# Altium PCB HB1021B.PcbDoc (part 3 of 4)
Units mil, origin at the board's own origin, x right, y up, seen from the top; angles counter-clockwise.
Board outline 4729.44 x 3075.9 mil, 2 copper layers (Top Layer, Bottom Layer); 113 components, 113 nets, 422 pads, 478 vias.
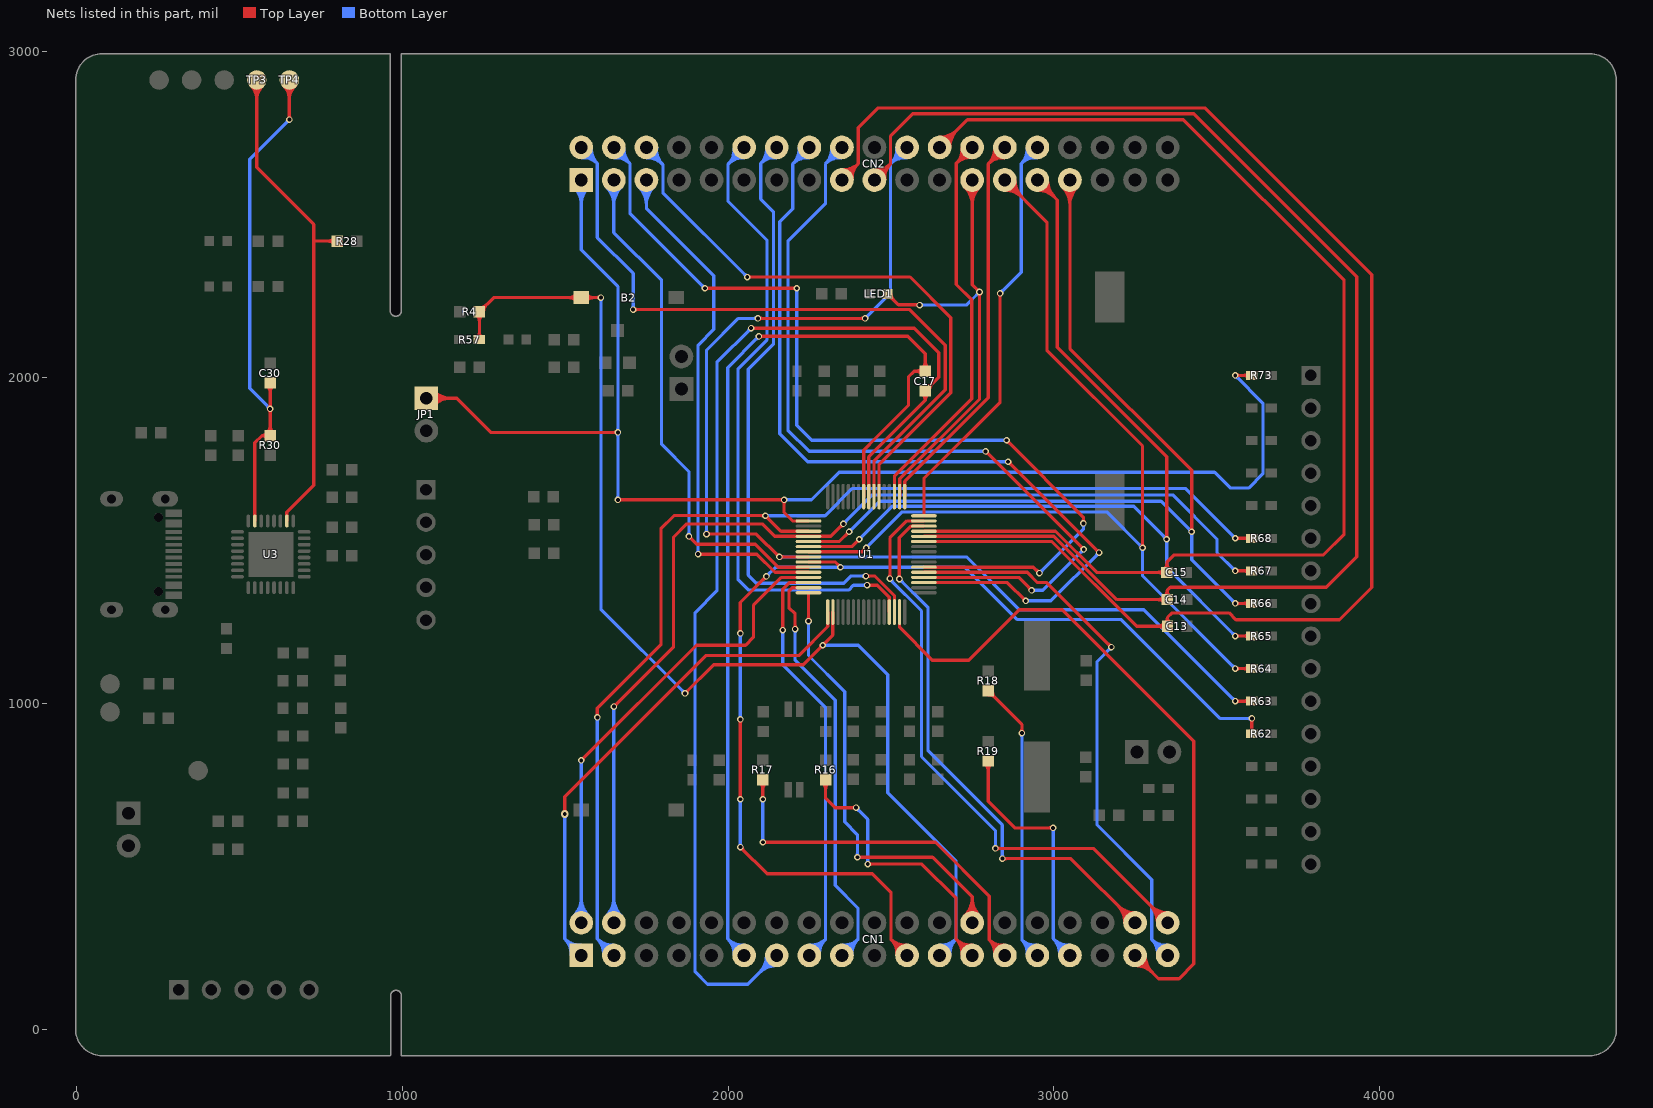
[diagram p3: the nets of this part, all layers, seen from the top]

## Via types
v1: diameter 20, hole 12, Top Layer to Bottom Layer, tented both sides, 451 vias
v2: diameter 23.62, hole 11.81, Top Layer to Bottom Layer, tented both sides, 20 vias
v3: diameter 122.05, hole 122.05, Top Layer to Bottom Layer, tented both sides, 4 vias
v4: diameter 39.37, hole 23.62, Top Layer to Bottom Layer, tented both sides, 2 vias
v5: diameter 30, hole 20, Top Layer to Bottom Layer, tented both sides, 1 vias

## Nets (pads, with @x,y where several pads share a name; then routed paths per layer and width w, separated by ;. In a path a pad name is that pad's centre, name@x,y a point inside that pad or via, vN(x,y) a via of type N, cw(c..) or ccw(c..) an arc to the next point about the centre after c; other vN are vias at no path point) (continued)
PB0: C13.1 CN2.17 U1.27 | length 4788.3
  Top Layer w10: CN2.17@2349.61,2606.79 2400,2657.18 ; CN2.17@2350.57,2628.18 ccw(c2352.57,2672.53) 2383.96,2641.14 ccw(c2415.35,2609.75) CN2.17@2371,2607.75 ; CN2.17@2351.02,2638.17 ccw(c2353.95,2703.22) 2400,2657.18 ; CN2.17@2380.99,2608.2 cw(c2446.04,2611.14) 2400,2657.18 ; U1.27@2601.43,1497.16 2994.42,1497.16 3254.57,1237 C13.1@3349,1237 3349,1264 ; C13.1@3340.16,1228.16 ccw(c3318.82,1206.82) 3318.82,1237 ccw(c3318.82,1267.18) C13.1@3340.16,1245.84 ; C13.1@3340.91,1246.53 ccw(c3326.09,1264) 3349,1264 ; C13.1@3357.09,1246.53 cw(c3371.91,1264) 3349,1264 ; 2400,2657.18 2400,2767 2461,2828 3464.09,2828 3976,2316.09 3976,1356 3877,1257 3559,1257 3538,1278 3363,1278 3349,1264
PB1: C14.1 CN2.19 U1.28 | length 4427.3
  Top Layer w10: CN2.19@2449.61,2606.79 2499.02,2656.2 ; CN2.19@2450.88,2628.17 ccw(c2453.4,2670.37) 2483.29,2640.47 ccw(c2513.18,2610.58) CN2.19@2470.99,2608.06 ; CN2.19@2451.48,2638.15 ccw(c2455.17,2700.05) 2499.02,2656.2 ; CN2.19@2480.97,2608.66 cw(c2542.87,2612.35) 2499.02,2656.2 ; U1.28@2601.43,1512.91 2999.88,1512.91 3193.79,1319 C14.1@3348,1319 3348,1347 ; C14.1@3339.16,1310.16 ccw(c3317.82,1288.82) 3317.82,1319 ccw(c3317.82,1349.18) C14.1@3339.16,1327.84 ; C14.1@3339.66,1328.31 ccw(c3322.89,1347) 3348,1347 ; C14.1@3356.35,1328.31 cw(c3373.11,1347) 3348,1347 ; 2499.02,2656.2 2499.02,2742.02 2567,2810 3430,2810 3930,2310 3930,1450 3837,1357 3358,1357 3348,1347
PB2: C15.1 CN2.24 U1.29 | length 3964.7
  Top Layer w10: U1.29@2601.43,1528.65 3005.35,1528.65 3131.89,1402.11 C15.1@3347.29,1402.11 3347.29,1433.29 3370,1456 3828,1456 3891,1519 3891,2299 3398,2792 2734.82,2792 CN2.24@2649.61,2706.79 ; CN2.24@2649.61,2728.21 ccw(c2649.61,2779.91) 2686.17,2743.35 ccw(c2722.73,2706.79) CN2.24@2671.02,2706.79 ; CN2.24@2649.61,2738.21 ccw(c2649.61,2814.05) 2703.24,2760.42 ccw(c2756.87,2706.79) CN2.24@2681.02,2706.79 ; C15.1@3338.45,1393.27 ccw(c3317.11,1371.93) 3317.11,1402.11 ccw(c3317.11,1432.28) 3338.45,1410.94 ccw(c3317.11,1432.28) 3347.29,1432.28 ccw(c3377.46,1432.28) C15.1@3356.13,1410.94
PB3: CN2.31 R66.1 U1.54 | length 3193.8
  Top Layer w10: U1.54@2247.1,1497.16 2342.1,1497.16 v1(2372,1527.06) ; v1@2367,1527.06 cw(c2354.93,1527.06) 2363.46,1518.52 cw(c2372,1509.98) v1@2372,1522.06 ; CN2.31@3027.39,2584.57 cw(c2973.76,2530.94) 3049.61,2530.94 cw(c3125.45,2530.94) CN2.31@3071.82,2584.57 ; CN2.31@3034.46,2591.64 cw(c2997.9,2555.08) 3049.61,2555.08 cw(c3101.31,2555.08) CN2.31@3064.75,2591.64 ; CN2.31@3049.61,2606.79 3049.61,2089.39 3423.34,1715.66 v1(3423.34,1527.06) ; v1@3419.8,1530.59 ccw(c3411.27,1539.13) 3423.34,1539.13 ccw(c3435.41,1539.13) v1@3426.87,1530.59 ; v1(3557,1307) R66.1@3608,1307 ; v1@3560.54,1303.46 cw(c3569.07,1294.93) 3569.07,1307 cw(c3569.07,1319.07) v1@3560.54,1310.54 ; R66.1@3598.07,1300.79 ccw(c3583.08,1285.8) 3583.08,1307 ccw(c3583.08,1328.2) R66.1@3598.07,1313.21
  Bottom Layer w10: v1(2372,1527.06) 2465.94,1621 3329.39,1621 v1(3423.34,1527.06) 3423.34,1440.66 v1(3557,1307) ; v1@2372,1532.06 ccw(c2372,1544.13) 2380.54,1535.59 ccw(c2389.07,1527.06) v1@2377,1527.06 ; v1@3418.34,1527.06 ccw(c3406.27,1527.06) 3414.8,1535.59 ccw(c3423.34,1544.13) v1@3423.34,1532.06 ; v1@3419.8,1523.52 cw(c3411.27,1514.98) 3423.34,1514.98 cw(c3435.41,1514.98) v1@3426.87,1523.52 ; v1@3552,1307 ccw(c3539.93,1307) 3548.46,1315.54 ccw(c3557,1324.07) v1@3557,1312
PB4: CN2.29 R65.1 U1.55 | length 3262.7
  Top Layer w10: U1.55@2247.1,1481.41 2380.41,1481.41 v1(2403,1504) ; v1@2398,1504 cw(c2385.93,1504) 2394.46,1495.46 cw(c2403,1486.93) v1@2403,1499 ; CN2.29@2949.61,2575.37 cw(c2949.61,2499.52) 3003.24,2553.16 cw(c3056.87,2606.79) CN2.29@2981.02,2606.79 ; CN2.29@2949.61,2585.37 cw(c2949.61,2533.67) 2986.17,2570.23 cw(c3022.73,2606.79) CN2.29@2971.02,2606.79 ; CN2.29@2949.61,2606.79 3011,2545.39 3011,2093 3346.39,1757.61 v1(3346.39,1504) ; v1@3342.86,1507.54 ccw(c3334.32,1516.07) 3346.39,1516.07 ccw(c3358.47,1516.07) v1@3349.93,1507.54 ; v1@3556,1207 v1(3557,1207) R65.1@3608,1207 ; v1@3560.54,1203.46 cw(c3569.07,1194.93) 3569.07,1207 cw(c3569.07,1219.07) v1@3560.54,1210.54 ; R65.1@3598.07,1200.79 ccw(c3583.08,1185.8) 3583.08,1207 ccw(c3583.08,1228.2) R65.1@3598.07,1213.21
  Bottom Layer w10: v1(2403,1504) 2504,1605 3245.39,1605 v1(3346.39,1504) ; v1@2403,1509 ccw(c2403,1521.07) 2411.54,1512.54 ccw(c2420.07,1504) v1@2408,1504 ; v1@3341.39,1504 ccw(c3329.32,1504) 3337.86,1512.54 ccw(c3346.39,1521.07) v1@3346.39,1509 ; v1@3342.86,1500.46 cw(c3334.32,1491.93) 3346.39,1491.93 cw(c3358.47,1491.93) v1@3349.93,1500.46 ; v1@3346.39,1504.61 v1(3346.39,1504) ; v1@3552,1207 ccw(c3539.93,1207) 3548.46,1215.54 ccw(c3557,1224.07) v1@3557,1212 ; v1(3557,1207) 3346.39,1417.61 v1(3346.39,1504)
PB5: CN2.27 R64.1 U1.56 | length 3331.4
  Top Layer w10: U1.56@2247.1,1465.66 2412.46,1465.66 v1(2424.27,1477.47) ; v1@2419.27,1477.47 cw(c2407.2,1477.47) 2415.73,1468.94 cw(c2424.27,1460.4) v1@2424.27,1472.47 ; CN2.27@2849.61,2575.37 cw(c2849.61,2499.52) 2903.24,2553.16 cw(c2956.87,2606.79) CN2.27@2881.02,2606.79 ; CN2.27@2849.61,2585.37 cw(c2849.61,2533.67) 2886.17,2570.23 cw(c2922.73,2606.79) CN2.27@2871.02,2606.79 ; CN2.27@2849.61,2606.79 2979,2477.39 2979,2084 3272.37,1790.63 v1(3272.37,1478.03) ; v1@3268.83,1481.56 ccw(c3260.3,1490.1) 3272.37,1490.1 ccw(c3284.44,1490.1) v1@3275.9,1481.56 ; v1(3557,1107) R64.1@3608,1107 ; v1@3560.54,1103.46 cw(c3569.07,1094.93) 3569.07,1107 cw(c3569.07,1119.07) v1@3560.54,1110.54 ; R64.1@3598.07,1100.79 ccw(c3583.08,1085.8) 3583.08,1107 ccw(c3583.08,1128.2) R64.1@3598.07,1113.21
  Bottom Layer w10: v1@2424.27,1478.03 2534.24,1588 3162.39,1588 v1(3272.37,1478.03) 3272.37,1391.63 v1(3557,1107) ; v1@2424.27,1482.47 ccw(c2424.27,1493.2) 2431.85,1485.62 ; v1@2429.27,1477.47 cw(c2442.68,1477.47) 2433.2,1486.96 ; v1@3267.37,1478.03 ccw(c3255.3,1478.03) 3263.83,1486.56 ccw(c3272.37,1495.1) v1@3272.37,1483.03 ; v1@3268.83,1474.49 cw(c3260.3,1465.96) 3272.37,1465.96 cw(c3284.44,1465.96) v1@3275.9,1474.49 ; v1@3552,1107 ccw(c3539.93,1107) 3548.46,1115.54 ccw(c3557,1124.07) v1@3557,1112
PB6: CN2.22 R63.1 U1.57 | length 4070.1
  Top Layer w10: v1(1934,1520) 2087,1520 2157.09,1449.91 U1.57@2247.1,1449.91 ; v1@1937.54,1516.46 cw(c1946.07,1507.93) 1946.07,1520 cw(c1946.07,1532.07) v1@1937.54,1523.54 ; v1(2092,2182) v1(2421,2182) ; v1@2095.54,2178.46 cw(c2104.07,2169.93) 2104.07,2182 cw(c2104.07,2194.07) v1@2095.54,2185.54 ; 2147.91,1459.09 ccw(c2158,1469.19) v1@2158,1454.91 ; 2150.11,1456.89 cw(c2143.13,1449.91) v1@2153,1449.91 ; v1@2161.54,1446.38 cw(c2170.07,1437.84) 2170.07,1449.91 cw(c2170.07,1461.98) v1@2161.54,1453.45 ; v1@2417.46,2178.46 ccw(c2408.93,2169.93) 2408.93,2182 ccw(c2408.93,2194.07) v1@2417.46,2185.54 ; v1(3557,1007) R63.1@3608,1007 ; v1@3560.54,1003.46 cw(c3569.07,994.93) 3569.07,1007 cw(c3569.07,1019.07) v1@3560.54,1010.54 ; R63.1@3598.07,1000.79 ccw(c3583.08,985.8) 3583.08,1007 ccw(c3583.08,1028.2) R63.1@3598.07,1013.21
  Bottom Layer w10: v1@1930.46,1523.54 ccw(c1921.93,1532.07) 1934,1532.07 ccw(c1946.07,1532.07) v1@1937.54,1523.54 ; v1(1934,1520) 1934,2084 2032,2182 v1(2092,2182) ; v1@2088.46,2178.46 ccw(c2079.93,2169.93) 2079.93,2182 ccw(c2079.93,2194.07) v1@2088.46,2185.54 ; v1(2158,1449.91) 2732.09,1449.91 2894,1288 3276,1288 v1(3557,1007) ; v1@2161.54,1446.38 cw(c2170.07,1437.84) 2170.07,1449.91 cw(c2170.07,1461.98) v1@2161.54,1453.45 ; v1(2421,2182) 2499.02,2260.02 2499.02,2656.2 ; v1@2421,2187 ccw(c2421,2199.07) 2429.54,2190.54 ccw(c2438.07,2182) v1@2426,2182 ; CN2.22@2518.22,2705.46 cw(c2452.55,2702.68) 2499.03,2656.21 ; CN2.22@2528.21,2705.88 cw(c2483.44,2703.99) 2515.13,2672.31 cw(c2546.81,2640.63) CN2.22@2548.7,2685.39 ; CN2.22@2548.28,2675.4 ccw(c2545.5,2609.73) 2499.03,2656.21 ; CN2.22@2549.61,2706.79 2499.02,2656.2 ; v1@3552,1007 ccw(c3539.93,1007) 3548.46,1015.54 ccw(c3557,1024.07) v1@3557,1012
PB7: CN1.21 R62.1 U1.58 | length 3938.2
  Top Layer w10: v1@2034.37,709.54 ccw(c2025.84,718.07) 2037.91,718.07 ccw(c2049.98,718.07) v1@2041.45,709.54 ; v1@2034.37,947.46 cw(c2025.84,938.93) 2037.91,938.93 cw(c2049.98,938.93) v1@2041.45,947.46 ; v1@2034.37,1218.54 ccw(c2025.84,1227.07) 2037.91,1227.07 ccw(c2049.98,1227.07) v1@2041.45,1218.54 ; v1@2037.91,553.91 cw(c2037.91,541.84) 2046.45,550.37 cw(c2054.98,558.91) v1@2042.91,558.91 ; v1(2037.91,558.91) 2119.82,477 2443.17,477 2500,420.17 2500,276.39 ; v1(2037.91,706) v1(2037.91,951) ; v1(2037.91,1215) 2037.91,1309.91 v1(2118,1390) ; v1@2113,1390 cw(c2100.93,1390) 2109.46,1381.46 cw(c2118,1372.93) v1@2118,1385 ; U1.58@2247.1,1434.17 2328.83,1434.17 v1(2345,1418) ; v1@2340,1418 ccw(c2327.93,1418) 2336.46,1426.54 ccw(c2345,1435.07) v1@2345,1423 ; CN1.21@2518.24,228.57 ccw(c2455.73,232.12) 2500,276.39 ; CN1.21@2528.22,228 ccw(c2485.61,230.42) 2515.79,260.6 ccw(c2545.97,290.78) CN1.21@2548.39,248.17 ; CN1.21@2547.82,258.15 cw(c2544.27,320.66) 2500,276.39 ; CN1.21@2549.61,226.79 2500,276.39 ; R62.1@3601.79,913.21 ccw(c3586.8,928.2) 3608,928.2 ccw(c3629.2,928.2) R62.1@3614.21,913.21 ; v1@3604.46,950.46 cw(c3595.93,941.93) 3608,941.93 cw(c3620.07,941.93) v1@3611.54,950.46 ; R62.1@3608,907 v1(3608,954)
  Bottom Layer w10: v1@2034.37,562.45 ccw(c2025.84,570.98) 2037.91,570.98 ccw(c2049.98,570.98) v1@2041.45,562.45 ; v1@2034.37,702.46 cw(c2025.84,693.93) 2037.91,693.93 cw(c2049.98,693.93) v1@2041.45,702.46 ; v1@2034.37,954.54 ccw(c2025.84,963.07) 2037.91,963.07 ccw(c2049.98,963.07) v1@2041.45,954.54 ; v1@2034.37,1211.46 cw(c2025.84,1202.93) 2037.91,1202.93 cw(c2049.98,1202.93) v1@2041.45,1211.46 ; v1(2037.91,558.91) v1(2037.91,706) ; v1(2037.91,951) v1(2037.91,1215) ; v1(2118,1390) 2146,1418 v1(2345,1418) 2727,1418 2887,1258 3206,1258 3510,954 v1(3608,954) ; v1@2118,1395 ccw(c2118,1407.07) 2126.54,1398.54 ccw(c2135.07,1390) v1@2123,1390 ; v1@2341.46,1414.46 ccw(c2332.93,1405.93) 2332.93,1418 ccw(c2332.93,1430.07) v1@2341.46,1421.54 ; v1@2348.54,1414.46 cw(c2357.07,1405.93) 2357.07,1418 cw(c2357.07,1430.07) v1@2348.54,1421.54 ; v1@3604.46,950.46 ccw(c3595.93,941.93) 3595.93,954 ccw(c3595.93,966.07) v1@3604.46,957.54
PB8: CN2.3 U1.59 | length 1833.8
  Top Layer w10: v1@1880,1508 cw(c1880,1495.93) 1888.54,1504.46 cw(c1897.07,1513) v1@1885,1513 ; v1(1880,1513) 1904,1489 2084,1489 2154.58,1418.42 U1.59@2247.1,1418.42
  Bottom Layer w10: CN2.3@1627.39,2584.57 cw(c1573.76,2530.94) 1649.61,2530.94 cw(c1725.45,2530.94) CN2.3@1671.82,2584.57 ; CN2.3@1634.46,2591.64 cw(c1597.9,2555.08) 1649.61,2555.08 cw(c1701.31,2555.08) CN2.3@1664.75,2591.64 ; CN2.3@1649.61,2606.79 1649.61,2445.39 1796,2299 1796,1796 1880,1712 v1(1880,1513) ; v1@1876.46,1516.54 ccw(c1867.93,1525.07) 1880,1525.07 ccw(c1892.07,1525.07) v1@1883.54,1516.54
PB9: CN2.5 U1.60 | length 1854.3
  Top Layer w10: v1(1908,1458.27) 2088.73,1458.27 2144.33,1402.67 U1.60@2247.1,1402.67 ; v1@1911.54,1454.73 cw(c1920.07,1446.2) 1920.07,1458.27 cw(c1920.07,1470.34) v1@1911.54,1461.8
  Bottom Layer w10: CN2.5@1727.39,2584.57 cw(c1673.76,2530.94) 1749.61,2530.94 cw(c1825.45,2530.94) CN2.5@1771.82,2584.57 ; CN2.5@1734.46,2591.64 cw(c1697.9,2555.08) 1749.61,2555.08 cw(c1801.31,2555.08) CN2.5@1764.75,2591.64 ; CN2.5@1749.61,2606.79 1749.61,2519.39 1956,2313 1956,2148 1908,2100 v1(1908,1458.27) ; v1@1904.46,1461.8 ccw(c1895.93,1470.34) 1908,1470.34 ccw(c1920.07,1470.34) v1@1911.54,1461.8
PB10: CN1.36 U1.30 | length 1990.3
  Top Layer w10: v1@2522.46,1385.54 ccw(c2513.93,1394.07) 2526,1394.07 ccw(c2538.07,1394.07) v1@2529.54,1385.54 ; v1(2526,1382) 2526,1508.77 2561.63,1544.4 U1.30@2601.43,1544.4 ; 2557.98,1540.75 cw(c2566.98,1531.75) 2566.98,1544.48 ccw(c2565.79,1534.89) 2558.95,1541.73 ; v1(2842,523.73) 3052.66,523.73 CN1.36@3249.61,326.79 ; v1@2845.54,520.2 cw(c2854.07,511.66) 2854.07,523.73 cw(c2854.07,535.8) v1@2845.54,527.27 ; CN1.36@3218.19,326.79 ccw(c3142.34,326.79) 3195.97,380.42 ccw(c3249.61,434.05) CN1.36@3249.61,358.21 ; CN1.36@3228.19,326.79 ccw(c3176.48,326.79) 3213.04,363.35 ccw(c3249.61,399.91) CN1.36@3249.61,348.21
  Bottom Layer w10: v1@2526,1377 cw(c2526,1364.93) 2534.54,1373.46 cw(c2543.07,1382) v1@2531,1382 ; v1(2526,1382) 2614,1294 2614,855 2842,627 v1(2842,523.73) ; v1@2838.46,527.27 ccw(c2829.93,535.8) 2842,535.8 ccw(c2854.07,535.8) v1@2845.54,527.27
PB11: CN1.38 U1.31 | length 2106.9
  Top Layer w10: v1@2493.46,1386.54 ccw(c2484.93,1395.07) 2497,1395.07 ccw(c2509.07,1395.07) v1@2500.54,1386.54 ; v1(2497,1383) 2497,1508 2549.15,1560.15 U1.31@2601.43,1560.15 ; v1(2821,555) 3121.39,555 CN1.38@3349.61,326.79 ; v1@2824.54,551.46 cw(c2833.07,542.93) 2833.07,555 cw(c2833.07,567.07) v1@2824.54,558.54 ; CN1.38@3318.19,326.79 ccw(c3242.34,326.79) 3295.97,380.42 ccw(c3349.61,434.05) CN1.38@3349.61,358.21 ; CN1.38@3328.19,326.79 ccw(c3276.48,326.79) 3313.04,363.35 ccw(c3349.61,399.91) CN1.38@3349.61,348.21
  Bottom Layer w10: v1(2497,1383) 2497,1381 2594,1284 2594,837 2821,610 v1(2821,555) ; v1@2502,1383 ccw(c2518.9,1383) 2506.95,1371.05 ; v1@2817.46,558.54 ccw(c2808.93,567.07) 2821,567.07 ccw(c2833.07,567.07) v1@2824.54,558.54
PB12: CN2.30 U1.32 | length 1490.4
  Top Layer w10: U1.32@2601.43,1575.9 2601.43,1690.43 2835,1924 v1(2835,2259) ; v1@2831.46,2255.46 cw(c2822.93,2246.93) 2835,2246.93 cw(c2847.07,2246.93) v1@2838.54,2255.46
  Bottom Layer w10: v1(2835,2259) 2900,2324 2900,2657.18 ; v1@2835,2264 ccw(c2835,2276.07) 2843.54,2267.54 ccw(c2852.07,2259) v1@2840,2259 ; CN2.30@2918.24,2705.01 cw(c2855.73,2701.46) 2900,2657.18 ; CN2.30@2928.22,2705.57 cw(c2885.61,2703.15) 2915.79,2672.97 cw(c2945.97,2642.79) CN2.30@2948.39,2685.41 ; CN2.30@2947.82,2675.42 ccw(c2944.27,2612.91) 2900,2657.18 ; CN2.30@2949.61,2706.79 2900,2657.18
PB13: CN2.28 U1.33 | length 1389.4
  Top Layer w10: U1.33@2542.38,1634.95 2542.38,1681.38 2799,1938 2799,2656.18 ; CN2.28@2818.22,2705.47 cw(c2752.48,2702.71) 2799,2656.18 ; CN2.28@2828.21,2705.89 cw(c2783.39,2704.01) 2815.11,2672.29 cw(c2846.83,2640.57) CN2.28@2848.71,2685.39 ; CN2.28@2848.29,2675.4 ccw(c2845.53,2609.66) 2799,2656.18 ; CN2.28@2849.61,2706.79 2799,2656.18
  Bottom Layer w10: CN2.28@2849.61,2699.62 CN2.28@2849.61,2706.79
PB14: CN2.25 LED1.2 U1.34 | length 1721.7
  Top Layer w10: LED1.2@2490,2247 cw(c2490,2222.86) 2507.07,2239.93 cw(c2524.14,2257) LED1.2@2500,2257 ; LED1.2@2490,2257 2523,2224 2587,2224 v1(2588,2223) ; U1.34@2526.63,1634.95 2527.38,1635.7 2527.38,1689.38 2772,1934 v1(2772,2263) 2749.61,2285.39 CN2.25@2749.61,2606.79 ; 2573.51,2224 cw(c2573.51,2208.51) v1@2584.46,2219.46 ; CN2.25@2727.39,2584.57 cw(c2673.76,2530.94) 2749.61,2530.94 cw(c2825.45,2530.94) CN2.25@2771.82,2584.57 ; CN2.25@2734.46,2591.64 cw(c2697.9,2555.08) 2749.61,2555.08 cw(c2801.31,2555.08) CN2.25@2764.75,2591.64 ; v1@2767,2263 ccw(c2754.93,2263) 2763.46,2271.54 ccw(c2772,2280.07) v1@2772,2268 ; v1@2768.46,2259.46 cw(c2759.93,2250.93) 2772,2250.93 cw(c2784.07,2250.93) v1@2775.54,2259.46
  Bottom Layer w10: v1(2588,2223) 2732,2223 v1(2772,2263) ; v1@2591.54,2219.46 cw(c2600.07,2210.93) 2600.07,2223 cw(c2600.07,2235.07) v1@2591.54,2226.54 ; v1@2767,2263 cw(c2754.93,2263) 2763.46,2254.46 cw(c2772,2245.93) v1@2772,2258
PB15: CN2.26 U1.35 | length 1381.2
  Top Layer w10: U1.35@2510.88,1634.95 2510.88,1697.88 2748,1935 2748,2239 2701,2286 2701,2658.18 ; CN2.26@2718.27,2704.53 cw(c2658.94,2700.25) 2701,2658.18 ; CN2.26@2728.24,2705.25 cw(c2687.8,2702.33) 2716.47,2673.65 cw(c2745.15,2644.98) CN2.26@2748.06,2685.43 ; CN2.26@2747.35,2675.45 ccw(c2743.06,2616.12) 2701,2658.18 ; CN2.26@2749.61,2706.79 2701,2658.18
PC0: CN2.12 U1.13 | length 2192.1
  Top Layer w10: v1(2427,1363) 2458,1363 2495.13,1325.87 U1.13@2495.13,1280.62 ; v1@2430.54,1359.46 cw(c2439.07,1350.93) 2439.07,1363 cw(c2439.07,1375.07) v1@2430.54,1366.54
  Bottom Layer w10: 2016.27,2671.27 ccw(c1986.81,2700.74) CN2.12@2028.29,2704.73 ; 2017.82,2672.82 cw(c2048.16,2642.49) CN2.12@2049.12,2685.38 ; CN2.12@2018.33,2703.78 cw(c1959.46,2698.11) 2001.28,2656.28 cw(c2047.43,2610.14) CN2.12@2048.9,2675.38 ; CN2.12@2049.61,2706.79 2049.61,2704.61 2000.19,2655.19 2000.19,2540.81 2120,2421 2120,2117 2031,2028 2031,1380 2063,1348 2370,1348 2385,1363 v1(2427,1363) ; v1@2423.46,1359.46 ccw(c2414.93,1350.93) 2414.93,1363 ccw(c2414.93,1375.07) v1@2423.46,1366.54
PC1: CN2.14 U1.14 | length 2140
  Top Layer w10: v1(2423,1391) 2451.21,1391 2510.88,1331.33 U1.14@2510.88,1280.62 ; v1@2426.54,1387.46 cw(c2435.07,1378.93) 2435.07,1391 cw(c2435.07,1403.07) v1@2426.54,1394.54
  Bottom Layer w10: CN2.14@2118.24,2704.92 cw(c2056.34,2701.22) 2100.19,2657.37 ; CN2.14@2128.23,2705.51 cw(c2086.03,2703) 2115.92,2673.1 cw(c2145.81,2643.21) CN2.14@2148.33,2685.41 ; CN2.14@2147.74,2675.43 ccw(c2144.04,2613.52) 2100.19,2657.37 ; CN2.14@2149.61,2706.79 2100.19,2657.37 ; v1@2419.46,1387.46 ccw(c2410.93,1378.93) 2410.93,1391 ccw(c2410.93,1403.07) v1@2419.46,1394.54 ; v1(2423,1391) 2377.17,1391 2355.17,1369 2087,1369 2062,1394 2062,2026 2140,2104 2140,2508.44 2100.19,2548.25 2100.19,2657.37
PC2: CN1.35 U1.15 | length 2336.9
  Top Layer w10: U1.15@2526.63,1280.62 2526.63,1233.37 2627,1133 2739,1133 2894,1288 3026.57,1288 3430,884.57 3430,200.52 3384.48,155 3321.39,155 CN1.35@3249.61,226.79 ; CN1.35@3249.61,195.37 cw(c3249.61,119.52) 3303.24,173.16 cw(c3356.87,226.79) CN1.35@3281.02,226.79 ; CN1.35@3249.61,205.37 cw(c3249.61,153.66) 3286.17,190.23 cw(c3322.73,226.79) CN1.35@3271.02,226.79
PC3: CN2.16 U1.19 | length 2966.4
  Top Layer w10: U1.19@2601.43,1371.17 2857.83,1371.17 v1(2914,1315) ; v1@2860,1737 cw(c2860,1724.93) 2868.54,1733.46 cw(c2877.07,1742) v1@2865,1742 ; v1(2860,1742) v1(3139,1463) ; v1@2909,1315 ccw(c2896.93,1315) 2905.46,1323.54 ccw(c2914,1332.07) v1@2914,1320 ; v1@3134,1463 ccw(c3121.93,1463) 3130.46,1471.54 ccw(c3139,1480.07) v1@3139,1468
  Bottom Layer w10: CN2.16@2218.22,2705.46 cw(c2152.55,2702.68) 2199.03,2656.21 ; CN2.16@2228.21,2705.88 cw(c2183.44,2703.99) 2215.13,2672.31 cw(c2246.81,2640.63) CN2.16@2248.7,2685.39 ; CN2.16@2248.28,2675.4 ccw(c2245.5,2609.73) 2199.03,2656.21 ; CN2.16@2249.61,2706.79 2199.02,2656.2 ; v1@2856.46,1738.46 ccw(c2847.93,1729.93) 2847.93,1742 ccw(c2847.93,1754.07) v1@2856.46,1745.54 ; v1(2860,1742) 2245,1742 2159,1828 2159,2478.31 2199.02,2518.33 2199.02,2656.2 ; v1(2914,1315) 2991,1315 v1(3139,1463) ; v1@2917.54,1311.46 cw(c2926.07,1302.93) 2926.07,1315 cw(c2926.07,1327.07) v1@2917.54,1318.54 ; v1@3134,1463 cw(c3121.93,1463) 3130.46,1454.46 cw(c3139,1445.93) v1@3139,1458
PC4: CN2.18 U1.20 | length 2852
  Top Layer w10: U1.20@2601.43,1386.92 2892.08,1386.92 v1(2931.76,1347.24) ; v1@2791,1769 cw(c2791,1756.93) 2799.54,1765.46 cw(c2808.07,1774) v1@2796,1774 ; v1(2791,1774) v1(3092,1473) ; v1@2926.76,1347.24 ccw(c2914.69,1347.24) 2923.23,1355.77 ccw(c2931.76,1364.31) v1@2931.76,1352.24 ; v1@3087,1473 ccw(c3074.93,1473) 3083.46,1481.54 ccw(c3092,1490.07) v1@3092,1478
  Bottom Layer w10: 2299,2627.28 2299,2656.18 ; 2299.02,2627.26 2299.02,2533.51 2184,2418.48 2184,1839 2249,1774 v1(2791,1774) ; CN2.18@2318.22,2705.47 cw(c2252.48,2702.71) 2299,2656.18 ; CN2.18@2328.21,2705.89 cw(c2283.39,2704.01) 2315.11,2672.29 cw(c2346.83,2640.58) CN2.18@2348.71,2685.39 ; CN2.18@2348.29,2675.4 ccw(c2345.53,2609.66) 2299,2656.18 ; CN2.18@2349.61,2706.79 2299,2656.18 ; v1@2787.46,1770.46 ccw(c2778.93,1761.93) 2778.93,1774 ccw(c2778.93,1786.07) v1@2787.46,1777.54 ; v1(2931.76,1347.24) 2966.24,1347.24 v1(3092,1473) ; v1@2935.3,1343.7 cw(c2943.83,1335.17) 2943.83,1347.24 cw(c2943.83,1359.31) v1@2935.3,1350.77 ; v1@3087,1473 cw(c3074.93,1473) 3083.46,1464.46 cw(c3092,1455.93) v1@3092,1468
PC5: CN1.37 U1.21 | length 1934.7
  Top Layer w10: U1.21@2601.43,1402.67 2918.33,1402.67 2950,1371 2979,1371 v1(3177,1173) ; v1@3172,1173 ccw(c3159.93,1173) 3168.46,1181.54 ccw(c3177,1190.07) v1@3177,1178
  Bottom Layer w10: v1@3172,1173 cw(c3159.93,1173) 3168.46,1164.46 cw(c3177,1155.93) v1@3177,1168 ; v1(3177,1173) 3132.61,1128.61 3132.61,627.35 3301,458.95 3301,275.39 ; CN1.37@3318.27,229.05 ccw(c3258.94,233.33) 3301,275.39 ; CN1.37@3328.24,228.33 ccw(c3287.8,231.25) 3316.47,259.92 ccw(c3345.15,288.6) CN1.37@3348.06,248.15 ; CN1.37@3347.35,258.12 cw(c3343.06,317.45) 3301,275.39 ; CN1.37@3349.61,226.79 3301,275.39
PC6: CN2.4 U1.22 | length 3203.3
  Top Layer w10: v1(1929,2274.5) v1(2211,2274.5) ; v1@1932.54,2270.96 cw(c1941.07,2262.43) 1941.07,2274.5 cw(c1941.07,2286.57) v1@1932.54,2278.04 ; v1@2207.46,2270.96 ccw(c2198.93,2262.43) 2198.93,2274.5 ccw(c2198.93,2286.57) v1@2207.46,2278.04 ; U1.22@2601.43,1418.42 2937.58,1418.42 v1(2956,1400) ; v1@2855,1803 cw(c2855,1790.93) 2863.54,1799.46 cw(c2872.07,1808) v1@2860,1808 ; v1(2855,1808) 3091,1572 v1(3091,1553) ; v1@2951,1400 ccw(c2938.93,1400) 2947.46,1408.54 ccw(c2956,1417.07) v1@2956,1405 ; v1@3087.46,1556.54 ccw(c3078.93,1565.07) 3091,1565.07 ccw(c3103.07,1565.07) v1@3094.54,1556.54
  Bottom Layer w10: CN2.4@1649.61,2706.79 1699.02,2657.37 ; CN2.4@1650.88,2685.41 cw(c1653.4,2643.21) 1683.29,2673.1 cw(c1713.19,2703) CN2.4@1670.99,2705.51 ; CN2.4@1651.48,2675.43 cw(c1655.17,2613.52) 1699.02,2657.37 ; CN2.4@1680.97,2704.92 ccw(c1742.87,2701.22) 1699.02,2657.37 ; v1@1924,2274.5 ccw(c1911.93,2274.5) 1920.46,2283.04 ccw(c1929,2291.57) v1@1929,2279.5 ; v1(1929,2274.5) 1699.02,2504.48 1699.02,2657.37 ; v1@2207.46,2270.96 cw(c2198.93,2262.43) 2211,2262.43 cw(c2223.07,2262.43) v1@2214.54,2270.96 ; v1(2211,2274.5) 2211,1854 2257,1808 v1(2855,1808) ; v1@2851.46,1804.46 ccw(c2842.93,1795.93) 2842.93,1808 ccw(c2842.93,1820.07) v1@2851.46,1811.54 ; v1(2956,1400) 3091,1535 v1(3091,1553) ; v1@2956,1405 ccw(c2956,1417.07) 2964.54,1408.54 ccw(c2973.07,1400) v1@2961,1400 ; v1@3087.46,1549.46 cw(c3078.93,1540.93) 3091,1540.93 cw(c3103.07,1540.93) v1@3094.54,1549.46
PC7: CN2.6 U1.38 | length 2063.9
  Top Layer w10: v1(2059,2309) 2559,2309 2684,2184 2684,1954 2463.64,1733.64 U1.38@2463.64,1634.95 ; v1@2062.54,2305.46 cw(c2071.07,2296.93) 2071.07,2309 cw(c2071.07,2321.07) v1@2062.54,2312.54
  Bottom Layer w10: CN2.6@1749.66,2685.37 cw(c1749.76,2639.82) 1781.97,2672.03 ; CN2.6@1749.61,2706.79 1749.61,2704.39 1800.19,2653.81 1800.19,2567.81 v1(2059,2309) ; CN2.6@1749.68,2675.37 cw(c1749.84,2605.86) 1798.99,2655.01 cw(c1843.12,2699.14) CN2.6@1780.92,2704.23 ; CN2.6@1770.95,2705.04 ccw(c1814.87,2701.45) 1783.71,2670.29 ; v1@2054,2309 ccw(c2041.93,2309) 2050.46,2317.54 ccw(c2059,2326.07) v1@2059,2314
PC8: CN2.2 U1.39 | length 2336.9
  Top Layer w10: v1(1709,2209) 2558,2209 2667,2100 2667,1963 2447.89,1743.89 U1.39@2447.89,1634.95 ; v1@1712.54,2205.46 cw(c1721.07,2196.93) 1721.07,2209 cw(c1721.07,2221.07) v1@1712.54,2212.54
  Bottom Layer w10: CN2.2@1549.61,2706.79 1599.02,2657.37 ; CN2.2@1550.88,2685.41 cw(c1553.4,2643.21) 1583.29,2673.1 cw(c1613.19,2703) CN2.2@1570.99,2705.51 ; CN2.2@1551.48,2675.43 cw(c1555.17,2613.52) 1599.02,2657.37 ; CN2.2@1580.97,2704.92 ccw(c1642.87,2701.22) 1599.02,2657.37 ; v1@1705.46,2212.54 ccw(c1696.93,2221.07) 1709,2221.07 ccw(c1721.07,2221.07) v1@1712.54,2212.54 ; v1(1709,2209) 1709,2320 1599.02,2429.98 1599.02,2657.37
PC9: CN2.1 JP1.1 R73.1 U1.50 | length 4850.3
  Top Layer w10: JP1.1@1074,1937 1167,1937 1272,1832 v1(1662,1832) ; JP1.1@1089.14,1921.86 cw(c1125.71,1885.29) 1125.71,1937 cw(c1125.71,1988.71) JP1.1@1089.14,1952.14 ; JP1.1@1096.21,1914.78 cw(c1149.85,1861.15) 1149.85,1937 cw(c1149.85,2012.85) JP1.1@1096.21,1959.22 ; v1@1658.46,1828.46 ccw(c1649.93,1819.93) 1649.93,1832 ccw(c1649.93,1844.07) v1@1658.46,1835.54 ; v1(1662,1625) 1662.11,1625.11 v1(2172,1625.11) 2172,1586.08 2197.93,1560.15 U1.50@2247.1,1560.15 ; v1@1665.54,1621.46 cw(c1674.34,1612.66) 1674.34,1625.11 ; v1@1665.54,1628.54 ccw(c1673.81,1636.81) 1673.81,1625.11 ; v1@2168.46,1628.65 cw(c2159.93,1637.18) 2159.93,1625.11 cw(c2159.93,1613.04) 2168.46,1621.57 cw(c2159.93,1613.04) 2172,1613.04 cw(c2184.07,1613.04) v1@2175.54,1621.57 ; v1(3557,2007) R73.1@3608,2007 ; v1@3560.54,2003.46 cw(c3569.07,1994.93) 3569.07,2007 cw(c3569.07,2019.07) v1@3560.54,2010.54 ; R73.1@3598.07,2000.79 ccw(c3583.08,1985.8) 3583.08,2007 ccw(c3583.08,2028.2) R73.1@3598.07,2013.21
  Bottom Layer w10: CN2.1@1527.39,2584.57 cw(c1473.76,2530.94) 1549.61,2530.94 cw(c1625.45,2530.94) CN2.1@1571.82,2584.57 ; CN2.1@1534.46,2591.64 cw(c1497.9,2555.08) 1549.61,2555.08 cw(c1601.31,2555.08) CN2.1@1564.75,2591.64 ; CN2.1@1549.61,2606.79 1549.61,2392.39 1662,2280 v1(1662,1832) v1(1662,1625) ; v1@1658.46,1628.54 ccw(c1649.93,1637.07) 1662,1637.07 ccw(c1674.07,1637.07) v1@1665.54,1628.54 ; v1@1658.46,1828.46 cw(c1649.93,1819.93) 1662,1819.93 cw(c1674.07,1819.93) v1@1665.54,1828.46 ; v1@1658.46,1835.54 ccw(c1649.93,1844.07) 1662,1844.07 ccw(c1674.07,1844.07) v1@1665.54,1835.54 ; v1(2172,1625.11) 2256.26,1625.11 2341.15,1710 3493.61,1710 3542.61,1661 3598,1661 3642,1705 3642,1922 v1(3557,2007) ; v1@2175.54,1621.57 cw(c2184.07,1613.04) 2184.07,1625.11 cw(c2184.07,1637.18) v1@2175.54,1628.65 ; v1@3557,2002 cw(c3557,1989.93) 3565.54,1998.46 cw(c3574.07,2007) v1@3562,2007
PC10: CN1.3 R68.1 U1.52 | length 3834.1
  Top Layer w10: v1@1595.49,960.54 ccw(c1586.95,969.07) 1599.02,969.07 ccw(c1611.1,969.07) v1@1602.56,960.54 ; v1(1599.02,957) 1599.02,985.02 1794,1180 1794,1536 1835,1577 2114.08,1577 v1(2115,1576.08) 2162.43,1528.65 U1.52@2247.1,1528.65 ; 2100.71,1577 cw(c2100.71,1561.79) v1@2111.46,1572.55 ; v1@2115,1571.08 cw(c2115,1559.01) 2123.54,1567.55 cw(c2132.07,1576.08) v1@2120,1576.08 ; v1(3557,1507) R68.1@3608,1507 ; v1@3560.54,1503.46 cw(c3569.07,1494.93) 3569.07,1507 cw(c3569.07,1519.07) v1@3560.54,1510.54 ; R68.1@3598.07,1500.79 ccw(c3583.08,1485.8) 3583.08,1507 ccw(c3583.08,1528.2) R68.1@3598.07,1513.21
  Bottom Layer w10: v1@1595.49,953.46 cw(c1586.95,944.93) 1599.02,944.93 cw(c1611.1,944.93) v1@1602.56,953.46 ; v1(1599.02,957) 1599.02,277.37 ; CN1.3@1618.22,228.12 ccw(c1552.56,230.9) 1599.03,277.37 ; CN1.3@1628.21,227.69 ccw(c1583.45,229.59) 1615.13,261.27 ccw(c1646.81,292.95) CN1.3@1648.7,248.19 ; CN1.3@1648.28,258.18 cw(c1645.5,323.84) 1599.03,277.37 ; CN1.3@1649.61,226.79 1599.02,277.37 ; v1(2115,1576.08) 2298.08,1576.08 2382,1660 3404,1660 v1(3557,1507) ; v1@2118.54,1572.55 cw(c2127.07,1564.01) 2127.07,1576.08 cw(c2127.07,1588.15) v1@2118.54,1579.62 ; v1@3552,1507 ccw(c3539.93,1507) 3548.46,1515.54 ccw(c3557,1524.07) v1@3557,1512
PC11: CN1.4 R67.1 U1.53 | length 3588.1
  Top Layer w10: v1(1649.61,990.39) 1833,1173.79 1833,1511 1873,1551 2105,1551 2143.09,1512.91 U1.53@2247.1,1512.91 2315.91,1512.91 v1(2354,1551) ; v1@1649.61,995.39 ccw(c1649.61,1007.46) 1658.14,998.93 ccw(c1666.68,990.39) v1@1654.61,990.39 ; v1@2349,1551 cw(c2336.93,1551) 2345.46,1542.46 cw(c2354,1533.93) v1@2354,1546 ; v1(3557,1407) R67.1@3608,1407 ; v1@3560.54,1403.46 cw(c3569.07,1394.93) 3569.07,1407 cw(c3569.07,1419.07) v1@3560.54,1410.54 ; R67.1@3598.07,1400.79 ccw(c3583.08,1385.8) 3583.08,1407 ccw(c3583.08,1428.2) R67.1@3598.07,1413.21
  Bottom Layer w10: CN1.4@1627.39,349 ccw(c1573.76,402.64) 1649.61,402.64 ccw(c1725.45,402.64) CN1.4@1671.82,349 ; CN1.4@1634.46,341.93 ccw(c1597.9,378.49) 1649.61,378.49 ccw(c1701.31,378.49) CN1.4@1664.75,341.93 ; v1@1646.07,986.86 cw(c1637.54,978.32) 1649.61,978.32 cw(c1661.68,978.32) v1@1653.14,986.86 ; CN1.4@1649.61,326.79 v1(1649.61,990.39) ; v1(2354,1551) 2443,1640 3365,1640 3501,1504 3501,1463 v1(3557,1407) ; v1@2354,1556 ccw(c2354,1568.07) 2362.54,1559.54 ccw(c2371.07,1551) v1@2359,1551 ; v1@3552,1407 ccw(c3539.93,1407) 3548.46,1415.54 ccw(c3557,1424.07) v1@3557,1412
PC12: CN1.1 U1.1 | length 1810.7
  Top Layer w10: v2@1494.21,665.54 ccw(c1482.58,677.17) 1499.02,677.17 ccw(c1515.47,677.17) v2@1503.84,665.54 ; v2(1499.02,660.72) 1499.02,714.02 1932,1147 2217,1147 2306.16,1236.16 U1.1@2306.16,1280.62
  Bottom Layer w10: v2@1494.21,655.91 cw(c1482.58,644.28) 1499.02,644.28 cw(c1515.47,644.28) v2@1503.84,655.91 ; v2(1499.02,660.72) 1499.02,277.37 ; CN1.1@1518.22,228.12 ccw(c1452.56,230.9) 1499.03,277.37 ; CN1.1@1528.21,227.69 ccw(c1483.45,229.59) 1515.13,261.27 ccw(c1546.81,292.95) CN1.1@1548.7,248.19 ; CN1.1@1548.28,258.18 cw(c1545.5,323.84) 1499.03,277.37 ; CN1.1@1549.61,226.79 1499.02,277.37
PC13: B2.2 CN1.23 R4.1 R57.1 U1.2 | length 4157.4
  Top Layer w10: R4.1@1228.16,2193.16 cw(c1206.82,2171.82) 1237,2171.82 cw(c1267.18,2171.82) R4.1@1245.84,2193.16 ; R57.1@1230.79,2123.21 ccw(c1215.81,2138.2) 1237,2138.2 ccw(c1258.2,2138.2) R57.1@1243.21,2123.21 ; R57.1@1237,2117 R4.1@1237,2202 1281,2246 B2.2@1549.61,2246 v1(1610,2246) ; R4.1@1237,2214.5 ccw(c1237,2244.68) 1258.34,2223.34 ccw(c1279.68,2202) R4.1@1249.5,2202 ; B2.2@1535.29,2235.62 ccw(c1510.22,2210.55) 1510.22,2246 ccw(c1510.22,2281.45) B2.2@1535.29,2256.38 ; B2.2@1563.93,2235.62 cw(c1589,2210.55) 1589,2246 cw(c1589,2281.45) B2.2@1563.93,2256.38 ; v1@1606.46,2242.46 ccw(c1597.93,2233.93) 1597.93,2246 ccw(c1597.93,2258.07) v1@1606.46,2249.54 ; v1(1868,1031) 1956,1119 2231,1119 2321.91,1209.91 U1.2@2321.91,1280.62 ; v1@1868,1036 ccw(c1868,1048.07) 1876.54,1039.54 ccw(c1885.07,1031) v1@1873,1031 ; v1@2285.77,1178.77 cw(c2273.7,1178.77) 2282.24,1170.24 cw(c2290.77,1161.7) v1@2290.77,1173.77 ; v1@2290.77,1183.77 ccw(c2290.77,1195.84) 2299.31,1187.31 ccw(c2307.84,1178.77) v1@2295.77,1178.77
  Bottom Layer w10: v1@1606.46,2242.46 cw(c1597.93,2233.93) 1610,2233.93 cw(c1622.07,2233.93) v1@1613.54,2242.46 ; v1(1610,2246) 1610,1289 v1(1868,1031) ; v1@1863,1031 ccw(c1850.93,1031) 1859.46,1039.54 ccw(c1868,1048.07) v1@1868,1036 ; v1(2290.77,1178.77) 2400.23,1178.77 2490.34,1088.66 2490.34,725.66 2700,516 2700,277.18 ; v1@2294.31,1175.24 cw(c2302.84,1166.7) 2302.84,1178.77 cw(c2302.84,1190.84) v1@2294.31,1182.31 ; CN1.23@2649.61,226.79 2700,277.18 ; CN1.23@2650.57,248.18 ccw(c2652.57,292.53) 2683.96,261.14 ccw(c2715.35,229.75) CN1.23@2671,227.75 ; CN1.23@2651.02,258.17 ccw(c2653.95,323.22) 2700,277.18 ; CN1.23@2680.99,228.2 cw(c2746.04,231.14) 2700,277.18
PC14: CN1.27 R17.1 | length 1445.1
  Top Layer w10: R17.1@2098.16,757.16 cw(c2076.82,735.82) 2107,735.82 cw(c2137.18,735.82) R17.1@2115.84,757.16 ; v1@2103.47,709.54 ccw(c2094.93,718.07) 2107,718.07 ccw(c2119.07,718.07) v1@2110.54,709.54 ; v1(2107,574) 2637,574 2802.19,408.81 2802.19,274.21 ; v1(2107,706) R17.1@2107,766 ; v1@2110.54,570.46 cw(c2119.07,561.93) 2119.07,574 cw(c2119.07,586.07) v1@2110.54,577.54 ; CN1.27@2818.32,229.64 ccw(c2762.7,234.71) 2802.19,274.2 ; CN1.27@2828.28,228.73 ccw(c2790.36,232.19) 2817.28,259.11 ccw(c2844.21,286.03) CN1.27@2847.66,248.12 ; CN1.27@2846.75,258.08 cw(c2841.68,313.7) 2802.19,274.2 ; CN1.27@2849.61,226.79 2802.19,274.21
  Bottom Layer w10: v1@2103.47,577.54 ccw(c2094.93,586.07) 2107,586.07 ccw(c2119.07,586.07) v1@2110.54,577.54 ; v1@2103.47,702.46 cw(c2094.93,693.93) 2107,693.93 cw(c2119.07,693.93) v1@2110.54,702.46 ; v1(2107,574) v1(2107,706)
PC15: CN1.25 R16.1 | length 1160.9
  Top Layer w10: R16.1@2290.77,757.16 cw(c2269.43,735.82) 2299.61,735.82 cw(c2329.78,735.82) R16.1@2308.45,757.16 ; R16.1@2299.61,766 2299.61,709.39 2329,680 v1(2393,680) ; v1@2389.46,676.46 ccw(c2380.93,667.93) 2380.93,680 ccw(c2380.93,692.07) v1@2389.46,683.54 ; v1(2429,507) 2595,507 2700,402 2700,276.39 ; v1@2432.54,503.46 cw(c2441.07,494.93) 2441.07,507 cw(c2441.07,519.07) v1@2432.54,510.54 ; CN1.25@2718.24,228.57 ccw(c2655.73,232.12) 2700,276.39 ; CN1.25@2728.22,228 ccw(c2685.61,230.42) 2715.79,260.6 ccw(c2745.97,290.78) CN1.25@2748.39,248.17 ; CN1.25@2747.82,258.15 cw(c2744.27,320.66) 2700,276.39 ; CN1.25@2749.61,226.79 2700,276.39
  Bottom Layer w10: v1@2393,675 cw(c2393,662.93) 2401.54,671.46 cw(c2410.07,680) v1@2398,680 ; v1(2393,680) 2429,644 v1(2429,507) ; v1@2425.46,510.54 ccw(c2416.93,519.07) 2429,519.07 ccw(c2441.07,519.07) v1@2432.54,510.54
PD0: C17.1 CN1.13 U1.40 | length 3820.5
  Top Layer w10: v1(2071,2152) 2572,2152 2647,2077 2647,2001.18 C17.1@2605.61,1959.79 2605.61,1930.06 ; v1@2074.54,2148.46 cw(c2083.07,2139.93) 2083.07,2152 cw(c2083.07,2164.07) v1@2074.54,2155.54 ; U1.40@2432.14,1634.95 2432.14,1756.6 2605.61,1930.06 ; C17.1@2596.86,1950.85 cw(c2576.51,1930.06) 2605.61,1930.06 ; C17.1@2605.61,1972.29 ccw(c2605.61,2002.47) 2626.95,1981.13 ccw(c2648.28,1959.79) C17.1@2618.11,1959.79 ; C17.1@2614.35,1950.85 ccw(c2634.7,1930.06) 2605.61,1930.06
  Bottom Layer w10: v1@2066,2152 cw(c2053.93,2152) 2062.46,2143.46 cw(c2071,2134.93) v1@2071,2147 ; v1(2071,2152) 1966,2047 1966,1346 1899,1279 1899,176 1937,138 2060.82,138 CN1.13@2149.61,226.79 ; CN1.13@2118.19,226.79 cw(c2042.34,226.79) 2095.97,173.16 cw(c2149.61,119.52) CN1.13@2149.61,195.37 ; CN1.13@2128.19,226.79 cw(c2076.48,226.79) 2113.04,190.23 cw(c2149.61,153.67) CN1.13@2149.61,205.37
PD1: C17.2 CN1.11 U1.41 | length 3346.6
  Top Layer w10: v1(2095,2127) 2552,2127 2605.61,2073.39 C17.2@2605.61,2019.79 2571.09,2019.79 2554,2002.7 2554,1915 2453.79,1814.8 2416.39,1777.4 U1.41@2416.39,1634.95 ; v1@2098.54,2123.46 cw(c2107.07,2114.93) 2107.07,2127 cw(c2107.07,2139.07) v1@2098.54,2130.54 ; C17.2@2596.77,2010.95 ccw(c2575.43,1989.61) 2575.43,2019.79 ccw(c2575.43,2049.97) 2596.77,2028.63 ccw(c2575.43,2049.97) 2605.61,2049.97 ccw(c2635.78,2049.97) C17.2@2614.45,2028.63
  Bottom Layer w10: CN1.11@2018.22,228.11 ccw(c1952.48,230.87) 1999,277.39 ; CN1.11@2028.21,227.69 ccw(c1983.39,229.57) 2015.11,261.28 ccw(c2046.83,293) CN1.11@2048.71,248.19 ; CN1.11@2048.29,258.18 cw(c2045.53,323.92) 1999,277.39 ; CN1.11@2049.61,226.79 1999,277.39 ; v1@2090,2127 cw(c2077.93,2127) 2086.46,2118.46 cw(c2095,2109.93) v1@2095,2122 ; v1(2095,2127) 1999,2031 1999,277.39
PD2: CN1.2 U1.61 | length 1724.3
  Top Layer w10: v1(1549.61,825.31) 1903.3,1179 2054,1179 2078,1203 2078,1301 2163.92,1386.92 U1.61@2247.1,1386.92 ; v1@1549.61,830.31 ccw(c1549.61,842.38) 1558.14,833.84 ccw(c1566.68,825.31) v1@1554.61,825.31
  Bottom Layer w10: CN1.2@1527.39,349 ccw(c1473.76,402.64) 1549.61,402.64 ccw(c1625.45,402.64) CN1.2@1571.82,349 ; CN1.2@1534.46,341.93 ccw(c1497.9,378.49) 1549.61,378.49 ccw(c1601.31,378.49) CN1.2@1564.75,341.93 ; v1@1546.07,821.77 cw(c1537.54,813.24) 1549.61,813.24 cw(c1561.68,813.24) v1@1553.14,821.77 ; CN1.2@1549.61,326.79 v1(1549.61,825.31)
PD3: CN1.15 U1.62 | length 1503.9
  Top Layer w10: v1@2164.46,1228.54 ccw(c2155.93,1237.07) 2168,1237.07 ccw(c2180.07,1237.07) v1@2171.54,1228.54 ; v1(2168,1225) 2168,1351 2188.17,1371.17 U1.62@2247.1,1371.17
  Bottom Layer w10: v1@2164.46,1221.46 cw(c2155.93,1212.93) 2168,1212.93 cw(c2180.07,1212.93) v1@2171.54,1221.46 ; v1(2168,1225) 2168,1119 2299.61,987.39 2299.61,276.79 2250.77,227.95 CN1.15@2249.61,227.95 ; CN1.15@2250.7,248.18 ccw(c2252.91,291.65) 2283.69,260.87 ccw(c2314.47,230.09) CN1.15@2271,227.88 ; CN1.15@2251.2,258.16 ccw(c2254.45,321.94) 2299.6,276.79 ccw(c2344.76,231.63) CN1.15@2280.98,228.39
PD4: CN1.17 U1.63 | length 1505.1
  Top Layer w10: v1@2202.46,1231.54 ccw(c2193.93,1240.07) 2206,1240.07 ccw(c2218.07,1240.07) v1@2209.54,1231.54 ; v1(2206,1228) 2206,1275 2187,1294 2187,1345 2197.43,1355.43 U1.63@2247.1,1355.43
  Bottom Layer w10: v1@2202.46,1224.46 cw(c2193.93,1215.93) 2206,1215.93 cw(c2218.07,1215.93) v1@2209.54,1224.46 ; v1(2206,1228) 2206,1133 2329.27,1009.73 2329.27,441.73 2399.02,371.98 2399.02,276.2 ; CN1.17@2349.61,226.79 2399.02,276.2 ; CN1.17@2350.88,248.17 ccw(c2353.4,290.37) 2383.29,260.47 ccw(c2413.18,230.58) CN1.17@2370.99,228.06 ; CN1.17@2351.48,258.15 ccw(c2355.17,320.05) 2399.02,276.2 ; CN1.17@2380.97,228.66 cw(c2442.87,232.35) 2399.02,276.2
PD5: CN1.26 U1.64 | length 1632.4
  Top Layer w10: v1@2243.57,1256.54 ccw(c2235.03,1265.07) 2247.1,1265.07 ccw(c2259.17,1265.07) v1@2250.64,1256.54 ; v1(2247.1,1253) U1.64@2247.1,1339.68 ; v1(2397.34,528) 2628,528 2749.61,406.39 CN1.26@2749.61,326.79 ; v1@2400.88,524.46 cw(c2409.42,515.93) 2409.42,528 cw(c2409.42,540.07) v1@2400.88,531.54 ; CN1.26@2727.39,349 ccw(c2673.76,402.64) 2749.61,402.64 ccw(c2825.45,402.64) CN1.26@2771.82,349 ; CN1.26@2734.46,341.93 ccw(c2697.9,378.49) 2749.61,378.49 ccw(c2801.31,378.49) CN1.26@2764.75,341.93
  Bottom Layer w10: v1@2243.57,1249.46 cw(c2235.03,1240.93) 2247.1,1240.93 cw(c2259.17,1240.93) v1@2250.64,1249.46 ; v1(2247.1,1253) 2247.1,1147.27 2358,1036.37 2358,637 2397.34,597.66 v1(2397.34,528) ; v1@2393.81,531.54 ccw(c2385.27,540.07) 2397.34,540.07 ccw(c2409.42,540.07) v1@2400.88,531.54
PF0: CN1.31 R19.2 | length 1043.8
  Top Layer w10: R19.2@2789.77,814.47 cw(c2768.43,793.13) 2798.61,793.13 cw(c2828.78,793.13) R19.2@2807.45,814.47 ; R19.2@2798.61,823.31 2798.61,699.39 2880,618 v1(2998,618) ; v1@2994.46,614.46 ccw(c2985.93,605.93) 2985.93,618 ccw(c2985.93,630.07) v1@2994.46,621.54
  Bottom Layer w10: v1@2994.46,614.46 cw(c2985.93,605.93) 2998,605.93 cw(c3010.07,605.93) v1@3001.54,614.46 ; v1(2998,618) 2998,278.39 ; CN1.31@3018.2,227.66 ccw(c2949.18,229.57) 2998,278.39 ; CN1.31@3028.2,227.38 ccw(c2981.14,228.68) 3014.43,261.97 ccw(c3047.71,295.25) CN1.31@3049.01,248.2 ; CN1.31@3048.74,258.19 cw(c3046.83,327.22) 2998,278.39 ; CN1.31@3049.61,226.79 2998,278.39
PF1: CN1.29 R18.2 | length 1125
  Top Layer w10: R18.2@2798.61,1026.81 cw(c2798.61,996.63) 2819.95,1017.97 cw(c2841.28,1039.31) R18.2@2811.11,1039.31 ; R18.2@2798.61,1039.31 2902.19,935.72 v1(2902.19,909) ; v1@2898.65,912.54 ccw(c2890.12,921.07) 2902.19,921.07 ccw(c2914.26,921.07) v1@2905.72,912.54
  Bottom Layer w10: v1@2898.65,905.46 cw(c2890.12,896.93) 2902.19,896.93 cw(c2914.26,896.93) v1@2905.72,905.46 ; v1(2902.19,909) 2902.19,274.21 ; CN1.29@2918.32,229.64 ccw(c2862.7,234.71) 2902.19,274.2 ; CN1.29@2928.28,228.73 ccw(c2890.36,232.19) 2917.28,259.11 ccw(c2944.21,286.03) CN1.29@2947.66,248.12 ; CN1.29@2946.75,258.08 cw(c2941.68,313.7) 2902.19,274.2 ; CN1.29@2949.61,226.79 2902.19,274.21
PRG_NRST: C30.1 R30.2 TP4.1 U3.7 | length 1920.5
  Top Layer w10: U3.7@547.39,1560.15 547.39,1800.09 569.61,1822.31 ; R30.2@584.61,1814.81 ccw(c569.61,1803.56) 569.61,1822.31 ; R30.2@584.61,1829.81 cw(c569.61,1841.05) 569.61,1822.31 ; R30.2@585.77,1831.14 ccw(c564.43,1852.48) 594.61,1852.48 ccw(c624.78,1852.48) R30.2@603.45,1831.14 ; C30.1@585.77,1975.47 cw(c564.43,1954.13) 594.61,1954.13 cw(c624.78,1954.13) C30.1@603.45,1975.47 ; v1@591.07,1900.77 cw(c582.54,1892.24) 594.61,1892.24 cw(c606.68,1892.24) v1@598.14,1900.77 ; v1@591.07,1907.84 ccw(c582.54,1916.38) 594.61,1916.38 ccw(c606.68,1916.38) v1@598.14,1907.84 ; C30.1@594.61,1984.31 v1(594.61,1904.31) R30.2@594.61,1822.31 569.61,1822.31 ; TP4.1@635.93,2896.11 cw(c593.25,2853.43) 653.61,2853.43 cw(c713.96,2853.43) TP4.1@671.28,2896.11 ; TP4.1@643,2903.18 cw(c617.39,2877.57) 653.61,2877.57 cw(c689.82,2877.57) TP4.1@664.21,2903.18 ; v1@650.07,2795.84 ccw(c641.54,2804.38) 653.61,2804.38 ccw(c665.68,2804.38) v1@657.14,2795.84 ; v1(653.61,2792.31) TP4.1@653.61,2913.79
  Bottom Layer w10: v1@589.61,1904.31 ccw(c577.54,1904.31) 586.07,1912.84 ccw(c594.61,1921.38) v1@594.61,1909.31 ; v1(594.61,1904.31) 531.61,1967.31 531.61,2670.31 v1(653.61,2792.31) ; v1@648.61,2792.31 cw(c636.54,2792.31) 645.07,2783.77 cw(c653.61,2775.24) v1@653.61,2787.31
PRG_SWCLK: R28.2 TP3.1 U3.2 | length 1731.5
  Top Layer w10: TP3.1@535.93,2896.11 cw(c493.25,2853.43) 553.61,2853.43 cw(c613.96,2853.43) TP3.1@571.28,2896.11 ; TP3.1@543,2903.18 cw(c517.39,2877.57) 553.61,2877.57 cw(c589.82,2877.57) TP3.1@564.21,2903.18 ; TP3.1@553.61,2913.79 553.61,2645.31 728.61,2470.31 728.61,1669.31 645.82,1586.52 U3.2@645.82,1560.15 ; 728.61,2419.31 R28.2@800.61,2419.31 ; R28.2@791.77,2410.47 ccw(c770.43,2389.13) 770.43,2419.31 ccw(c770.43,2449.49) R28.2@791.77,2428.15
